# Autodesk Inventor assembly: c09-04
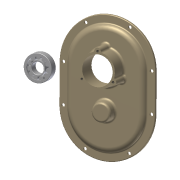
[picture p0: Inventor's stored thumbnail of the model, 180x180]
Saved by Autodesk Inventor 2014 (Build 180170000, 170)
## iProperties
Created: 2010-12
Part Number: c09-04
Document SubType Name: Assembly
Designer: Thom Tremblay
Author: Thom Tremblay
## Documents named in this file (3)
- C:\Inventor 2014 Essentials\Assemblies\Chapter 09\c09-04.iam
- C:\Inventor 2014 Essentials\Parts\Chapter 09\c09-10.ipt
- C:\Inventor 2014 Essentials\Assemblies\Chapter 09\Design Accelerators\Bearing c09-01.iam
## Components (2 placed, 2 different names)
1. c09-10:1
2. Bearing:1 [sub-assembly]
